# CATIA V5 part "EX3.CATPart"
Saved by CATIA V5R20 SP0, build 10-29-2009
Part number: EX3
Bounding box of the stored display mesh (mm): x 0 to 125, y 0 to 100, z 0 to 10
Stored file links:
  E:\Nouveau dossier\tarek\mécaniquee\Catia\TP 0\EX3.CATPart
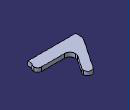
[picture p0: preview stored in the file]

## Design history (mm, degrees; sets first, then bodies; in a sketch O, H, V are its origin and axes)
Set1
  DatumSurface1 to DatumSurface13
Body1 (main body)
